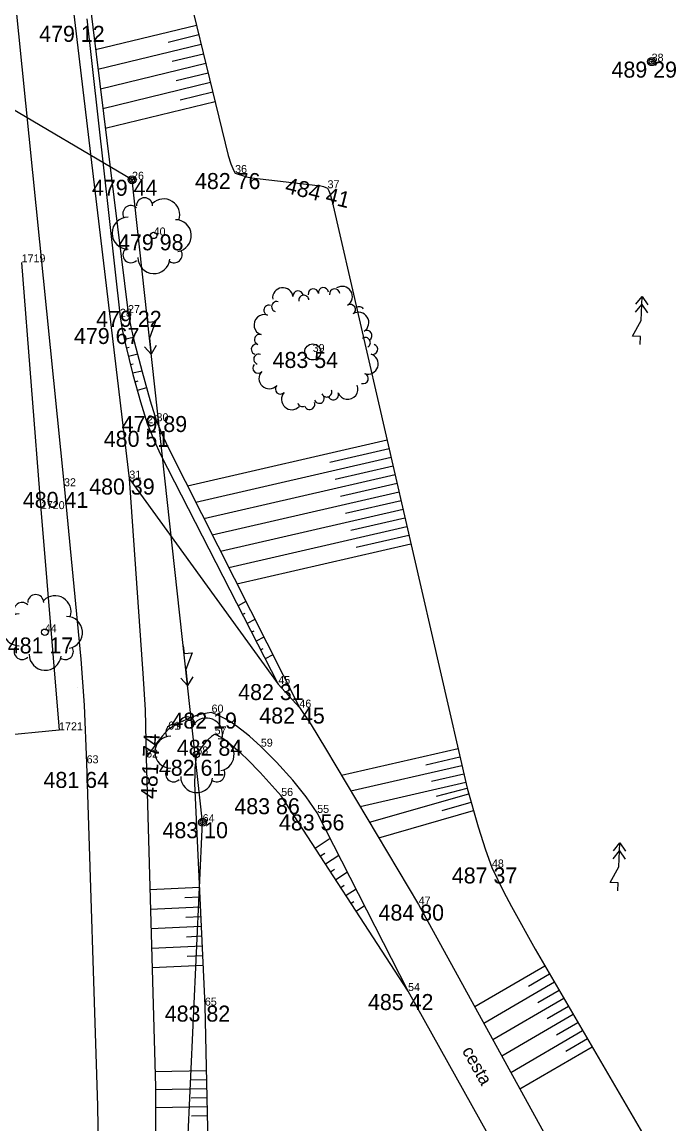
# Model space of a CAD drawing. Extents: x -559180 to -551373, y -1076947 to -1072071.
# Drawn here: x -553549.9 to -553509, y -1076087.1 to -1076018.2 of the extents above; entities that cross this region are included whole.
import ezdxf

# ---------------------------------------------------------------- set-up
doc = ezdxf.new("R2010")
doc.units = 0
for name, color, linetype in [('12_PLOTY', 7, 'Continuous'), ('17_KOMUNIKACE', 7, 'Continuous'), ('1_VODA_ZN', 7, 'Continuous'), ('20_EL_ZN', 7, 'Continuous'), ('26_SRAFY', 7, 'Continuous'), ('27_HRANA_PATA', 7, 'Continuous'), ('34_ZELEN', 7, 'Continuous'), ('3_BODY', 7, 'Continuous'), ('52_POPIS_UCELOVY', 7, 'Continuous'), ('6_VYSKY', 7, 'Continuous'), ('NNnadzemní', 7, 'Continuous')]:
    doc.layers.add(name, color=color, linetype=linetype)

# ---------------------------------------------------------------- blocks, each defined once
blk = doc.blocks.new('SLB')
at = {"layer": '20_EL_ZN'}
for radius in [0.25, 0.158, 0.05]:
    blk.add_circle((0, 0), radius, dxfattribs=at)
blk = doc.blocks.new('SLDP')
at = {"layer": '20_EL_ZN'}
for radius in [0.25, 0.158, 0.05]:
    blk.add_circle((0, 0), radius, dxfattribs=at)
blk = doc.blocks.new('POINT_DISPLAY')
blk.add_line((0, 0), (0, 0))
blk = doc.blocks.new('STLV')
at = {"layer": '34_ZELEN'}
blk.add_circle((0, 0), 0.5, dxfattribs=at)
for centre, radius, start, end in [((-1.866, 3.377), 0.64, 7.27905, 187.27905), ((-0.914, 3.498), 0.32, 7.27905, 187.27905), ((-0.552, 3.222), 0.32, 97.27905, 188.08122), ((-0.556, 3.222), 0.32, 6.47688, 97.27905), ((0.038, 3.62), 0.32, 7.27905, 187.27905), ((0.673, 3.701), 0.32, 7.27905, 187.27905), ((1.372, 3.62), 0.32, 7.27905, 187.27905), ((1.839, 3.46), 0.64, 302.42635, 122.42635), ((-2.733, 2.607), 0.32, 72.13175, 252.13175), ((-2.248, 2.834), 0.32, 72.13175, 252.13175), ((2.354, 2.649), 0.32, 302.42635, 122.42635), ((2.893, 2.511), 0.32, 32.42635, 123.22852), ((-3.027, 1.693), 0.64, 72.13175, 252.13175), ((2.869, 1.839), 0.64, 302.42635, 122.42635), ((-3.322, 0.779), 0.32, 72.13175, 252.13175), ((3.287, 0.583), 0.32, 32.42635, 123.22852), ((3.383, 1.029), 0.32, 302.42635, 122.42635), ((3.285, 0.587), 0.32, 301.62418, 32.42635), ((-3.518, 0.17), 0.32, 72.13175, 252.13175), ((3.746, 0.168), 0.32, 252.13175, 72.13175), ((-3.366, -0.453), 0.32, 72.13175, 252.13175), ((3.452, -0.746), 0.64, 252.13175, 72.13175), ((-3.419, -1.001), 0.32, 136.98445, 316.98445), ((-2.717, -1.656), 0.64, 136.98445, 316.98445), ((3.157, -1.66), 0.32, 252.13175, 72.13175), ((-2.015, -2.311), 0.32, 136.98445, 316.98445), ((-1.313, -2.966), 0.64, 136.98445, 316.98445), ((0.877, -2.497), 0.32, 201.03498, 291.83715), ((0.873, -2.499), 0.32, 291.83715, 22.63931), ((1.293, -2.675), 0.32, 201.83715, 21.83715), ((2.185, -2.318), 0.64, 201.83715, 21.83715), ((-0.639, -3.093), 0.32, 201.03498, 291.83715), ((-0.192, -3.27), 0.32, 201.83715, 21.83715), ((0.402, -2.891), 0.32, 201.83715, 21.83715)]:
    blk.add_arc(centre, radius, start, end, dxfattribs=at)
blk.add_blockref('POINT_DISPLAY', (0, 0), dxfattribs=at)
blk = doc.blocks.new('STLS')
at = {"layer": '34_ZELEN'}
blk.add_circle((0, 0), 0.2, dxfattribs=at)
for centre, radius, start, end in [((-0.571, 1.853), 0.5, 0, 180), ((0.636, 1.281), 1, 341.22932, 135), ((-1.425, 1.366), 0.5, 45, 210.43255), ((-1.599, 0.146), 1, 90, 270), ((1.356, -0.015), 1, 279.52997, 90), ((-1.424, -1.207), 0.5, 135, 315), ((1.283, -1.208), 0.5, 234.37768, 31.04793), ((0.019, -1.381), 1, 180, 353.84032)]:
    blk.add_arc(centre, radius, start, end, dxfattribs=at)
blk = doc.blocks.new('ELNN')
at = {"layer": '20_EL_ZN'}
for p, q in [((0, 0), (0.5, 0)), ((0.5, 0), (0.5, 0.5)), ((0.5, 0.5), (1.5, 0)), ((1.5, 0), (2.5, 0))]:
    blk.add_line(p, q, dxfattribs=at)
blk.add_lwpolyline([(2, 0.375), (2.5, 0), (2, -0.375)], dxfattribs=at)
blk = doc.blocks.new('ELVN')
at = {"layer": '20_EL_ZN'}
for p, q in [((0, 0), (0.5, 0)), ((0.5, 0), (0.5, 0.5)), ((0.5, 0.5), (1.5, 0)), ((1.5, 0), (2.5, 0)), ((2.5, 0), (3, 0))]:
    blk.add_line(p, q, dxfattribs=at)
for points in [[(2, 0.375), (2.5, 0), (2, -0.375)], [(2.5, 0.375), (3, 0), (2.5, -0.375)]]:
    blk.add_lwpolyline(points, dxfattribs=at)

msp = doc.modelspace()

# ---------------------------------------------------------------- linework, layer by layer
at = {"layer": '12_PLOTY'}
for p, q in [((-553549.94, -1076033.22), (-553548.74, -1076048.64)), ((-553548.74, -1076048.64), (-553547.6, -1076062.46)), ((-553547.6, -1076062.46), (-553552.89, -1076062.97))]:
    msp.add_line(p, q, dxfattribs=at)
at = {"layer": '17_KOMUNIKACE'}
for p, q in [((-553550.6, -1076014.27), (-553547.29, -1076047.21)), ((-553547.11, -1076014.07), (-553543.21, -1076046.73)), ((-553543.21, -1076046.73), (-553533.9, -1076059.57)), ((-553533.9, -1076059.57), (-553532.58, -1076061.04)), ((-553525.79, -1076078.75), (-553531.47, -1076067.62)), ((-553525.13, -1076073.35), (-553515.9, -1076090.13)), ((-553518.27, -1076092.18), (-553525.79, -1076078.75))]:
    msp.add_line(p, q, dxfattribs=at)
for points in [[(-553547.29, -1076047.21), (-553546.235, -1076058.013), (-553546.028, -1076060.884), (-553545.88, -1076064.52)], [(-553543.21, -1076046.73), (-553542.361, -1076058.901), (-553542.213, -1076061.18), (-553542.16, -1076064.16)], [(-553532.58, -1076061.04), (-553531.851, -1076062.117), (-553530.941, -1076063.589), (-553525.13, -1076073.35)], [(-553538.07, -1076061.35), (-553538.339, -1076061.388), (-553538.672, -1076061.446), (-553539.019, -1076061.536), (-553539.341, -1076061.649), (-553539.684, -1076061.795), (-553540.05, -1076061.977), (-553540.371, -1076062.15), (-553540.78, -1076062.41)], [(-553534.99, -1076063.48), (-553535.703, -1076062.835), (-553535.984, -1076062.59), (-553536.449, -1076062.25), (-553536.834, -1076061.969), (-553537.211, -1076061.74), (-553537.67, -1076061.503), (-553538.07, -1076061.35)], [(-553540.78, -1076062.41), (-553541.14, -1076062.794), (-553541.499, -1076063.234), (-553542.16, -1076064.16)], [(-553531.47, -1076067.62), (-553532.154, -1076066.609), (-553532.99, -1076065.565), (-553534.003, -1076064.448), (-553534.99, -1076063.48)], [(-553545.88, -1076064.52), (-553545.192, -1076085.921), (-553545.11, -1076091.16)], [(-553542.16, -1076064.16), (-553541.583, -1076084.737), (-553541.59, -1076091.22)]]:
    msp.add_lwpolyline(points, dxfattribs=at)
at = {"layer": '26_SRAFY'}
for p, q in [((-553545.319, -1076019.929), (-553539.012, -1076018.393)), ((-553540.78, -1076019.455), (-553538.867, -1076018.989)), ((-553545.168, -1076021.156), (-553538.722, -1076019.585)), ((-553540.531, -1076020.658), (-553538.577, -1076020.182)), ((-553545.017, -1076022.382), (-553538.431, -1076020.778)), ((-553540.283, -1076021.861), (-553538.286, -1076021.374)), ((-553544.866, -1076023.609), (-553538.141, -1076021.971)), ((-553540.034, -1076023.064), (-553537.995, -1076022.567)), ((-553544.715, -1076024.836), (-553537.85, -1076023.163)), ((-553542.966, -1076037.922), (-553543.51, -1076038.041)), ((-553543.22, -1076038.538), (-553543.389, -1076038.578)), ((-553542.688, -1076038.966), (-553543.263, -1076039.103)), ((-553542.961, -1076039.586), (-553543.138, -1076039.628)), ((-553542.41, -1076040.01), (-553543.013, -1076040.154)), ((-553542.685, -1076040.649), (-553542.862, -1076040.699)), ((-553542.132, -1076041.054), (-553542.715, -1076041.219)), ((-553539.571, -1076047.184), (-553527.099, -1076044.317)), ((-553530.677, -1076045.708), (-553526.975, -1076044.857)), ((-553539.057, -1076048.203), (-553526.851, -1076045.397)), ((-553530.349, -1076046.769), (-553526.727, -1076045.937)), ((-553538.543, -1076049.222), (-553526.602, -1076046.477)), ((-553530.02, -1076047.831), (-553526.478, -1076047.017)), ((-553538.029, -1076050.241), (-553526.354, -1076047.557)), ((-553537.515, -1076051.26), (-553526.106, -1076048.637)), ((-553529.692, -1076048.893), (-553526.23, -1076048.097)), ((-553529.364, -1076049.955), (-553525.982, -1076049.177)), ((-553537, -1076052.279), (-553525.857, -1076049.717)), ((-553536.486, -1076053.298), (-553525.609, -1076050.797)), ((-553529.036, -1076051.016), (-553525.733, -1076050.257)), ((-553535.92, -1076054.42), (-553536.415, -1076054.675)), ((-553535.985, -1076055.15), (-553536.132, -1076055.226)), ((-553535.361, -1076055.527), (-553535.849, -1076055.777)), ((-553535.42, -1076056.254), (-553535.565, -1076056.329)), ((-553534.803, -1076056.634), (-553535.282, -1076056.88)), ((-553534.856, -1076057.358), (-553534.999, -1076057.432)), ((-553534.244, -1076057.741), (-553534.715, -1076057.983)), ((-553529.942, -1076065.267), (-553522.667, -1076063.594)), ((-553524.677, -1076064.613), (-553522.546, -1076064.123)), ((-553529.359, -1076066.246), (-553522.424, -1076064.651)), ((-553524.332, -1076065.646), (-553522.303, -1076065.18)), ((-553528.777, -1076067.224), (-553522.181, -1076065.708)), ((-553528.194, -1076068.203), (-553521.997, -1076066.42)), ((-553524.014, -1076066.566), (-553522.097, -1076066.074)), ((-553523.663, -1076067.472), (-553521.845, -1076066.949)), ((-553527.612, -1076069.181), (-553521.693, -1076067.478)), ((-553530.65, -1076069.227), (-553531.588, -1076069.837)), ((-553531.002, -1076070.156), (-553531.268, -1076070.329)), ((-553530.114, -1076070.278), (-553530.948, -1076070.821)), ((-553530.393, -1076071.16), (-553530.628, -1076071.313)), ((-553529.577, -1076071.329), (-553530.308, -1076071.805)), ((-553529.784, -1076072.164), (-553529.988, -1076072.297)), ((-553541.929, -1076072.404), (-553538.831, -1076072.261)), ((-553529.041, -1076072.381), (-553529.668, -1076072.789)), ((-553541.895, -1076073.625), (-553538.775, -1076073.481)), ((-553539.736, -1076072.914), (-553538.803, -1076072.871)), ((-553529.175, -1076073.168), (-553529.348, -1076073.281)), ((-553528.504, -1076073.432), (-553529.028, -1076073.773)), ((-553539.686, -1076074.134), (-553538.747, -1076074.09)), ((-553541.86, -1076074.845), (-553538.719, -1076074.7)), ((-553539.637, -1076075.353), (-553538.691, -1076075.31)), ((-553541.826, -1076076.066), (-553538.663, -1076075.92)), ((-553539.587, -1076076.573), (-553538.634, -1076076.529)), ((-553541.792, -1076077.286), (-553538.606, -1076077.139)), ((-553521.624, -1076079.723), (-553517.238, -1076077.168)), ((-553518.263, -1076078.443), (-553516.943, -1076077.674)), ((-553521.059, -1076080.749), (-553516.648, -1076078.18)), ((-553517.681, -1076079.459), (-553516.354, -1076078.686)), ((-553520.495, -1076081.776), (-553516.059, -1076079.192)), ((-553517.099, -1076080.475), (-553515.764, -1076079.698)), ((-553519.93, -1076082.802), (-553515.47, -1076080.204)), ((-553516.517, -1076081.492), (-553515.175, -1076080.71)), ((-553519.366, -1076083.829), (-553514.88, -1076081.216)), ((-553515.935, -1076082.508), (-553514.585, -1076081.722)), ((-553518.801, -1076084.855), (-553514.291, -1076082.228)), ((-553541.61, -1076083.773), (-553538.405, -1076083.706)), ((-553539.358, -1076084.288), (-553538.393, -1076084.268)), ((-553541.604, -1076084.898), (-553538.382, -1076084.83)), ((-553539.339, -1076085.413), (-553538.37, -1076085.392)), ((-553541.599, -1076086.023), (-553538.358, -1076085.955)), ((-553539.321, -1076086.537), (-553538.346, -1076086.517))]:
    msp.add_line(p, q, dxfattribs=at)
at = {"layer": '27_HRANA_PATA'}
for p, q in [((-553545.81, -1076015.95), (-553543.29, -1076036.39)), ((-553545.86, -1076018), (-553543.79, -1076036.62)), ((-553525.79, -1076078.75), (-553533.72, -1076066.56))]:
    msp.add_line(p, q, dxfattribs=at)
for points in [[(-553540.8, -1076010.31), (-553540.804, -1076010.512), (-553540.787, -1076010.845), (-553540.755, -1076011.145), (-553540.688, -1076011.484), (-553540.552, -1076012.073), (-553537.029, -1076026.534), (-553536.863, -1076027.071), (-553536.75, -1076027.365), (-553536.679, -1076027.506), (-553536.6, -1076027.64)], [(-553536.6, -1076027.64), (-553536.406, -1076027.717), (-553536.145, -1076027.803), (-553535.892, -1076027.872), (-553535.58, -1076027.94), (-553531.42, -1076028.419), (-553531.241, -1076028.443), (-553531.08, -1076028.485), (-553530.923, -1076028.539), (-553530.82, -1076028.59)], [(-553530.82, -1076028.59), (-553530.735, -1076028.753), (-553530.659, -1076028.951), (-553530.526, -1076029.41), (-553522.097, -1076066.074), (-553521.403, -1076068.486), (-553520.951, -1076069.929), (-553520.55, -1076071.03)], [(-553543.79, -1076036.62), (-553543.647, -1076037.414), (-553543.443, -1076038.35), (-553542.993, -1076040.237), (-553542.515, -1076041.926), (-553542.09, -1076043.28)], [(-553543.29, -1076036.39), (-553543.122, -1076037.244), (-553542.911, -1076038.158), (-553542.401, -1076040.059), (-553541.909, -1076041.882), (-553541.51, -1076043.15)], [(-553541.51, -1076043.15), (-553541.089, -1076044.124), (-553540.734, -1076044.879), (-553532.58, -1076061.04)], [(-553542.09, -1076043.28), (-553541.665, -1076044.361), (-553541.266, -1076045.234), (-553533.9, -1076059.57)], [(-553537.88, -1076062.72), (-553537.942, -1076062.755), (-553538.066, -1076062.843), (-553538.286, -1076063.033), (-553538.45, -1076063.2), (-553538.73, -1076063.544), (-553538.885, -1076063.755), (-553539.02, -1076063.97)], [(-553533.72, -1076066.56), (-553535.035, -1076065.094), (-553535.821, -1076064.291), (-553536.229, -1076063.912), (-553536.572, -1076063.614), (-553537.16, -1076063.122), (-553537.5, -1076062.893), (-553537.592, -1076062.837), (-553537.706, -1076062.782), (-553537.798, -1076062.746), (-553537.88, -1076062.72)], [(-553539.02, -1076063.97), (-553539.106, -1076064.801), (-553539.121, -1076065.178), (-553539.13, -1076065.79), (-553538.49, -1076079.66)], [(-553520.55, -1076071.03), (-553519.828, -1076072.534), (-553519.333, -1076073.458), (-553517.839, -1076076.136), (-553511.15, -1076087.62)], [(-553538.49, -1076079.66), (-553538.329, -1076087.342), (-553538.092, -1076106.347), (-553538.21, -1076114.72)]]:
    msp.add_lwpolyline(points, dxfattribs=at)
at = {"layer": 'NNnadzemní'}
for p, q in [((-553543.04, -1076028.06), (-553572.09, -1076010.97)), ((-553538.63, -1076068.2), (-553543.04, -1076028.06)), ((-553540.34, -1076105.4), (-553538.63, -1076068.2))]:
    msp.add_line(p, q, dxfattribs=at)

# ---------------------------------------------------------------- block references
at = {"layer": '1_VODA_ZN'}
for p in [(-553510.57, -1076020.68), (-553543.04, -1076028.06), (-553536.6, -1076027.64), (-553530.82, -1076028.59), (-553541.69, -1076031.54), (-553543.79, -1076036.62), (-553543.29, -1076036.39), (-553531.75, -1076038.82), (-553541.51, -1076043.15), (-553542.09, -1076043.28), (-553547.29, -1076047.21), (-553543.21, -1076046.73), (-553548.74, -1076048.64), (-553548.49, -1076056.33), (-553546.473, -1076059.757), (-553546.47, -1076059.76), (-553533.9, -1076059.57), (-553532.58, -1076061.04), (-553538.07, -1076061.35), (-553547.6, -1076062.46), (-553540.78, -1076062.41), (-553537.88, -1076062.72), (-553534.99, -1076063.48), (-553545.88, -1076064.52), (-553542.16, -1076064.16), (-553539.02, -1076063.97), (-553533.72, -1076066.56), (-553531.47, -1076067.62), (-553538.63, -1076068.2), (-553520.55, -1076071.03), (-553525.13, -1076073.35), (-553525.79, -1076078.75), (-553538.49, -1076079.66)]:
    msp.add_blockref('POINT_DISPLAY', p, dxfattribs=at)
at = {"layer": '20_EL_ZN'}
for name, p in [('SLDP', (-553510.57, -1076020.68)), ('SLB', (-553543.04, -1076028.06)), ('SLB', (-553538.63, -1076068.2))]:
    msp.add_blockref(name, p, dxfattribs=at)
for name, p, xscale, yscale, rotation in [('ELVN', (-553511.289, -1076038.356), 0.9999977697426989, 0.9999977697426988, 87.67014759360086), ('ELNN', (-553542.117, -1076036.464), 1.000001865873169, 1.000001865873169, -83.73040305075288), ('ELNN', (-553539.842, -1076057.172), 1.000001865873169, 1.000001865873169, -83.73040305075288), ('ELVN', (-553512.678, -1076072.496), 0.9999977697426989, 0.9999977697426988, 87.67014759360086)]:
    msp.add_blockref(name, p, dxfattribs=dict(at, xscale=xscale, yscale=yscale, rotation=rotation))
at = {"layer": '34_ZELEN'}
for name, p in [('STLS', (-553541.69, -1076031.54)), ('STLV', (-553531.75, -1076038.82)), ('STLS', (-553548.49, -1076056.33)), ('STLS', (-553539.02, -1076063.97))]:
    msp.add_blockref(name, p, dxfattribs=at)

# ---------------------------------------------------------------- texts
at = {"layer": '3_BODY'}
for s, p in [('38', (-553510.57, -1076020.68)), ('36', (-553536.6, -1076027.64)), ('26', (-553543.04, -1076028.06)), ('37', (-553530.82, -1076028.59)), ('40', (-553541.69, -1076031.54)), ('1719', (-553549.94, -1076033.22)), ('28', (-553543.79, -1076036.62)), ('27', (-553543.29, -1076036.39)), ('39', (-553531.75, -1076038.82)), ('29', (-553542.09, -1076043.28)), ('30', (-553541.51, -1076043.15)), ('31', (-553543.21, -1076046.73)), ('32', (-553547.29, -1076047.21)), ('1720', (-553548.74, -1076048.64)), ('44', (-553548.49, -1076056.33)), ('45', (-553533.9, -1076059.57)), ('60', (-553538.07, -1076061.35)), ('46', (-553532.58, -1076061.04)), ('1721', (-553547.6, -1076062.46)), ('61', (-553540.78, -1076062.41)), ('57', (-553537.88, -1076062.72)), ('59', (-553534.99, -1076063.48)), ('62', (-553542.16, -1076064.16)), ('58', (-553539.02, -1076063.97)), ('63', (-553545.88, -1076064.52)), ('56', (-553533.72, -1076066.56)), ('55', (-553531.47, -1076067.62)), ('64', (-553538.63, -1076068.2)), ('48', (-553520.55, -1076071.03)), ('47', (-553525.13, -1076073.35)), ('54', (-553525.79, -1076078.75)), ('65', (-553538.49, -1076079.66))]:
    msp.add_text(s, height=0.5, dxfattribs=at).set_placement(p)
at = {"layer": '52_POPIS_UCELOVY'}
msp.add_text('cesta', height=0.8, rotation=299.24623, dxfattribs=at).set_placement((-553522.44, -1076082.481))
at = {"layer": '6_VYSKY'}
for s, p in [('479 12', (-553548.842, -1076019.442)), ('489 29', (-553513.075, -1076021.68)), ('479 44', (-553545.545, -1076029.06)), ('482 76', (-553539.105, -1076028.64)), ('479 98', (-553543.915, -1076032.469)), ('479 22', (-553545.28, -1076037.25)), ('479 67', (-553546.669, -1076038.322)), ('483 54', (-553534.255, -1076039.82)), ('479 89', (-553543.688, -1076043.822)), ('480 51', (-553544.806, -1076044.748)), ('480 39', (-553545.715, -1076047.73)), ('480 41', (-553549.865, -1076048.561)), ('481 17', (-553550.807, -1076057.658)), ('482 31', (-553536.405, -1076060.57)), ('482 45', (-553535.085, -1076062.04)), ('482 19', (-553540.575, -1076062.35)), ('482 84', (-553540.244, -1076064.048)), ('482 61', (-553541.361, -1076065.298)), ('481 64', (-553548.572, -1076066.058)), ('483 86', (-553536.645, -1076067.7)), ('483 56', (-553533.858, -1076068.713)), ('483 10', (-553541.135, -1076069.2)), ('487 37', (-553523.055, -1076072.03)), ('484 80', (-553527.635, -1076074.35)), ('485 42', (-553528.295, -1076079.937)), ('483 82', (-553540.995, -1076080.66))]:
    msp.add_text(s, height=1, dxfattribs=at).set_placement(p)
for s, rotation, p in [('484 41', 345.98779, (-553533.536, -1076028.856)), ('481 74', 87.34227, (-553541.496, -1076066.763))]:
    msp.add_text(s, height=1, rotation=rotation, dxfattribs=at).set_placement(p)

doc.saveas('drawing.dxf')
